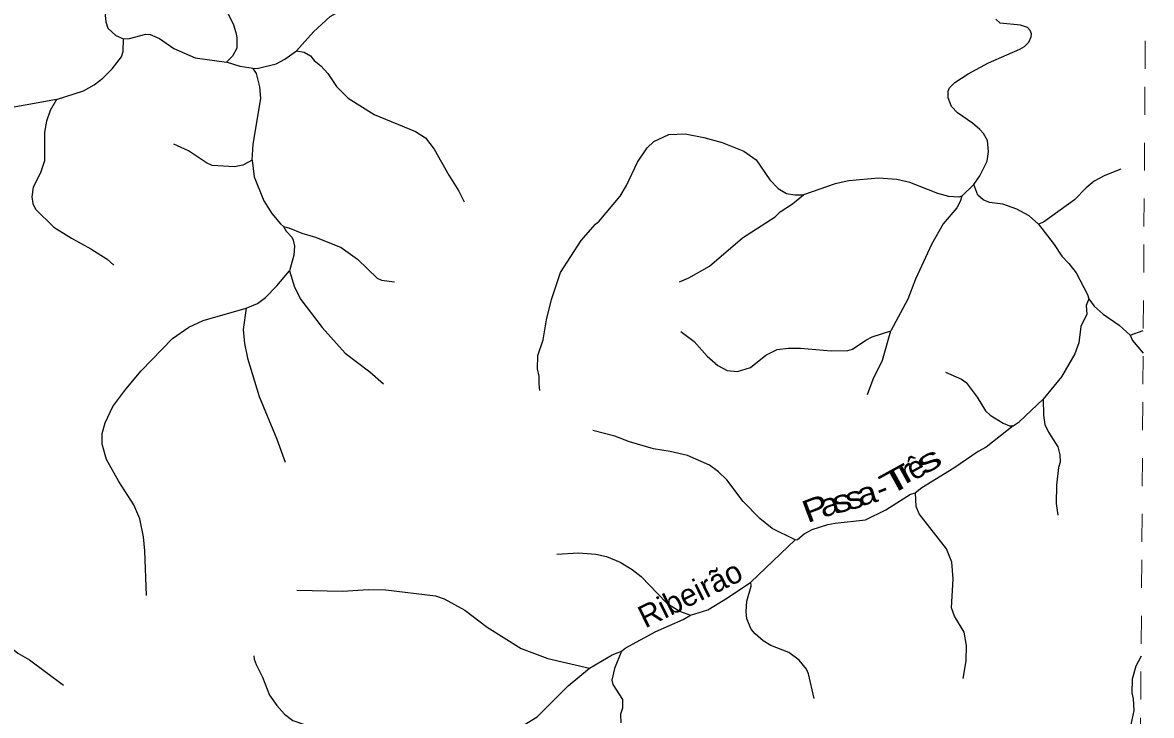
# Model space of a CAD drawing. Extents: x 577 to 602.9, y 7483.8 to 7511.6.
# Drawn here: x 598.702 to 602.746, y 7488.237 to 7490.719 of the extents above; entities that cross this region are included whole.
import ezdxf
from ezdxf.enums import TextEntityAlignment as Align

# ---------------------------------------------------------------- set-up
doc = ezdxf.new("R2010")
doc.units = 0
doc.header["$LTSCALE"] = 0.032
doc.linetypes.add('SHORT_DASHED', pattern=[2.7, 1.5, -1.2])
doc.layers.add('53', color=7, linetype='SHORT_DASHED', lineweight=13)
doc.layers.add('7', color=7, linetype='Continuous', lineweight=25)
doc.layers.add('61', color=7, linetype='Continuous')

msp = doc.modelspace()

# ---------------------------------------------------------------- linework, layer by layer
at = {"layer": '53'}
msp.add_lwpolyline([(602.6772, 7483.7754), (602.681, 7484.3402), (602.6848, 7484.9051), (602.6886, 7485.4699), (602.6924, 7486.0347), (602.6962, 7486.5996), (602.7, 7487.1644), (602.7038, 7487.7293), (602.7076, 7488.2941), (602.7115, 7488.859), (602.7153, 7489.4238), (602.7191, 7489.9887), (602.7229, 7490.5535), (602.7267, 7491.1183), (602.7305, 7491.6832), (602.7343, 7492.248), (602.7381, 7492.8129), (602.7419, 7493.3777), (602.7457, 7493.9426)], dxfattribs=at)
at = {"layer": '7'}
for p, q in [((598.8234, 7490.4436), (598.5928, 7490.4018)), ((602.6701, 7489.6), (602.7166, 7489.6157)), ((601.311, 7488.7142), (601.4702, 7488.866))]:
    msp.add_line(p, q, dxfattribs=at)
for points in [[(599.0212, 7491.3305), (599.0171, 7491.3174), (599.0196, 7491.091), (599.0131, 7491.0509), (599.0106, 7490.9929), (599.0155, 7490.9504), (599.0245, 7490.9169), (599.0294, 7490.8556), (599.0253, 7490.8302), (599.0032, 7490.7746), (598.9975, 7490.7444), (599, 7490.7215), (599.0081, 7490.6994), (599.0359, 7490.6733), (599.0637, 7490.661)], [(599.6833, 7490.6185), (599.7438, 7490.6856), (599.8035, 7490.7411), (599.8803, 7490.7828), (599.9375, 7490.8041), (599.9686, 7490.8196), (600.0152, 7490.849), (600.043, 7490.8719), (600.0822, 7490.9226), (600.0969, 7490.9488), (600.1231, 7491.0248), (600.1296, 7491.055), (600.1476, 7491.0951), (600.1582, 7491.1335), (600.1815, 7491.1819)], [(599.3357, 7490.9565), (599.3384, 7490.9349), (599.3547, 7490.8964), (599.4005, 7490.8065), (599.4397, 7490.7477), (599.4577, 7490.7109), (599.4659, 7490.6839), (599.47, 7490.6651), (599.47, 7490.6275), (599.4545, 7490.5989), (599.4321, 7490.577)], [(602.1094, 7490.1395), (602.1315, 7490.1698), (602.1568, 7490.2229), (602.1625, 7490.2572), (602.1584, 7490.2965), (602.1437, 7490.3218), (602.1306, 7490.3357), (602.1045, 7490.3586), (602.0514, 7490.3962), (602.0293, 7490.4191), (602.0178, 7490.4493), (602.0178, 7490.4738), (602.0219, 7490.4853), (602.0415, 7490.5041), (602.089, 7490.536), (602.1625, 7490.5752), (602.2745, 7490.6242), (602.2909, 7490.6332), (602.3064, 7490.6488), (602.3154, 7490.6684), (602.3162, 7490.679), (602.3113, 7490.6913), (602.3015, 7490.7019), (602.277, 7490.7093), (602.2042, 7490.7166), (602.1879, 7490.7313)], [(598.8234, 7490.4436), (598.9207, 7490.4747), (598.9583, 7490.4959), (598.9893, 7490.5196), (599.0229, 7490.5539), (599.0564, 7490.5965), (599.0629, 7490.6161), (599.0637, 7490.661)], [(599.0637, 7490.661), (599.085, 7490.662), (599.1438, 7490.6774), (599.1594, 7490.6766), (599.1929, 7490.6618), (599.2436, 7490.6267), (599.3204, 7490.5932), (599.4321, 7490.577)], [(599.528, 7490.5548), (599.5476, 7490.5556), (599.6106, 7490.5711), (599.6416, 7490.5883), (599.6833, 7490.6185)], [(599.6833, 7490.6185), (599.7103, 7490.6136), (599.7332, 7490.6005), (599.7471, 7490.5834), (599.7708, 7490.5646), (599.7953, 7490.5368), (599.8264, 7490.4902), (599.8689, 7490.4485), (599.9621, 7490.3896), (600.1092, 7490.3292), (600.1452, 7490.3063), (600.177, 7490.2654), (600.2285, 7490.1722), (600.2653, 7490.115), (600.2834, 7490.077)], [(599.528, 7490.5548), (599.4814, 7490.5621), (599.4321, 7490.577)], [(599.5247, 7490.2262), (599.5288, 7490.2842), (599.5558, 7490.4469), (599.5525, 7490.4886), (599.5403, 7490.537), (599.528, 7490.5548)], [(598.8234, 7490.4436), (598.8005, 7490.4044), (598.7874, 7490.3659), (598.7809, 7490.3267), (598.7809, 7490.2245), (598.7662, 7490.1812), (598.74, 7490.1297), (598.7351, 7490.0954), (598.7384, 7490.0709), (598.7482, 7490.0504), (598.8144, 7489.9859), (598.8774, 7489.9466), (598.9468, 7489.909), (599.0049, 7489.8714), (599.0288, 7489.8499)], [(600.5548, 7489.4014), (600.553, 7489.4235), (600.5522, 7489.4521), (600.5465, 7489.4791), (600.5481, 7489.5265), (600.5669, 7489.5829), (600.5792, 7489.6548), (600.5972, 7489.7275), (600.6291, 7489.824), (600.7034, 7489.9384), (600.7541, 7489.9973), (600.7672, 7490.0079), (600.8424, 7490.0978), (600.8653, 7490.1354), (600.9045, 7490.2188), (600.9389, 7490.2703), (600.9634, 7490.2932), (601.0173, 7490.3177), (601.0754, 7490.3202), (601.1424, 7490.3079), (601.2086, 7490.2899), (601.2863, 7490.258), (601.3296, 7490.227), (601.3794, 7490.1559), (601.4089, 7490.1248), (601.4383, 7490.1068), (601.4689, 7490.1019), (601.4992, 7490.102)], [(599.5247, 7490.2262), (599.4912, 7490.2082), (599.4618, 7490.2025), (599.3817, 7490.2074), (599.3605, 7490.2172), (599.2967, 7490.2597), (599.2436, 7490.2842)], [(599.5247, 7490.2262), (599.5313, 7490.1665), (599.5664, 7490.0807), (599.595, 7490.0357), (599.6261, 7489.9981), (599.6371, 7489.9883)], [(602.6367, 7490.1937), (602.5786, 7490.1714), (602.541, 7490.151), (602.5124, 7490.1273), (602.4699, 7490.0839), (602.3588, 7490.004), (602.3415, 7489.9973)], [(602.0662, 7490.0978), (602.0554, 7490.0937), (602.0195, 7490.0962), (601.9811, 7490.1068), (601.8805, 7490.1461), (601.8339, 7490.1567), (601.7685, 7490.1624), (601.6623, 7490.1526), (601.6132, 7490.142), (601.4992, 7490.102)], [(602.3415, 7489.9973), (602.3072, 7490.0267), (602.2639, 7490.0504), (602.2132, 7490.0692), (602.1658, 7490.0749), (602.1429, 7490.0848), (602.1241, 7490.1011), (602.1094, 7490.1395), (602.0662, 7490.0978)], [(601.0554, 7489.7903), (601.0893, 7489.8044), (601.1628, 7489.8469), (601.2814, 7489.9482), (601.3974, 7490.0235), (601.4162, 7490.0414), (601.4604, 7490.07), (601.4992, 7490.102)], [(602.0662, 7490.0978), (602.0603, 7490.0782), (602.0481, 7490.0561), (601.9999, 7489.9981), (601.9574, 7489.9237), (601.9001, 7489.8003), (601.8732, 7489.7284), (601.8119, 7489.6147)], [(599.6371, 7489.9883), (599.6564, 7489.9834), (599.7021, 7489.9646), (599.752, 7489.9499), (599.8435, 7489.9139), (599.9024, 7489.8714), (599.9727, 7489.8036), (599.9882, 7489.7962), (600.0344, 7489.7904)], [(599.6371, 7489.9883), (599.6465, 7489.972), (599.6662, 7489.9507), (599.6719, 7489.9393), (599.676, 7489.918), (599.6735, 7489.8861), (599.6581, 7489.8293)], [(602.3415, 7489.9973), (602.3979, 7489.9245), (602.4249, 7489.882), (602.4502, 7489.8567), (602.4756, 7489.8232), (602.5173, 7489.7455), (602.5211, 7489.73)], [(599.5035, 7489.6965), (599.5435, 7489.7128), (599.5722, 7489.7341), (599.613, 7489.7758), (599.6581, 7489.8293)], [(599.6581, 7489.8293), (599.6768, 7489.7717), (599.6989, 7489.7267), (599.7749, 7489.627), (599.8574, 7489.5346), (599.9465, 7489.4684), (599.9945, 7489.4248)], [(602.5211, 7489.73), (602.5116, 7489.7063), (602.514, 7489.6744), (602.4928, 7489.6303), (602.4854, 7489.5722), (602.4715, 7489.5322), (602.4241, 7489.4504), (602.3579, 7489.3703)], [(602.5211, 7489.73), (602.541, 7489.7038), (602.5729, 7489.6744), (602.6301, 7489.6352), (602.6701, 7489.6)], [(599.1458, 7488.667), (599.1406, 7488.8268), (599.1357, 7488.8766), (599.1226, 7488.9412), (599.1005, 7488.9911), (599.0474, 7489.0753), (599.0032, 7489.1545), (598.9869, 7489.2085), (598.9877, 7489.2477), (598.9983, 7489.2853), (599.0261, 7489.3434), (599.0719, 7489.4055), (599.1275, 7489.4717), (599.2395, 7489.587), (599.2983, 7489.6278), (599.349, 7489.6523), (599.5035, 7489.6965)], [(599.5035, 7489.6965), (599.4929, 7489.6197), (599.497, 7489.569), (599.5084, 7489.5167), (599.5493, 7489.3793), (599.613, 7489.2265), (599.6428, 7489.1448)], [(601.0603, 7489.6121), (601.1081, 7489.5763), (601.1547, 7489.524), (601.1923, 7489.4905), (601.2266, 7489.4725), (601.2634, 7489.4692), (601.3091, 7489.484), (601.3647, 7489.5273), (601.4056, 7489.5477), (601.4448, 7489.5526), (601.489, 7489.5526), (601.5985, 7489.5428), (601.6582, 7489.5445), (601.6745, 7489.5494), (601.7228, 7489.5821), (601.7456, 7489.5935), (601.8119, 7489.6147)], [(601.7293, 7489.3867), (601.7489, 7489.4415), (601.7824, 7489.5093), (601.8119, 7489.6147)], [(602.6701, 7489.6), (602.6783, 7489.5804), (602.7161, 7489.5353)], [(602.0077, 7489.4666), (602.0652, 7489.4423), (602.0816, 7489.43), (602.1217, 7489.3777), (602.1519, 7489.3287), (602.1682, 7489.3123), (602.2148, 7489.2837), (602.2377, 7489.2747), (602.2508, 7489.2747)], [(602.2508, 7489.2747), (602.2721, 7489.2886), (602.3579, 7489.3703)], [(602.3579, 7489.3703), (602.3587, 7489.3123), (602.3644, 7489.2796), (602.3767, 7489.2518), (602.411, 7489.1995), (602.4176, 7489.1709), (602.4184, 7489.1447), (602.4126, 7489.1251), (602.4053, 7489.0622), (602.4045, 7488.9968), (602.4106, 7488.9548)], [(601.4702, 7488.866), (601.3876, 7488.9069), (601.3427, 7488.9428), (601.283, 7489.0041), (601.225, 7489.0818), (601.1955, 7489.1104), (601.1628, 7489.1341), (601.0844, 7489.1684), (601.0214, 7489.1832), (600.9618, 7489.1921), (600.8767, 7489.2175), (600.8236, 7489.2379), (600.7454, 7489.2577)], [(602.2508, 7489.2747), (602.1543, 7489.1979), (602.1249, 7489.1832), (602.0383, 7489.1227), (601.9238, 7489.0524), (601.9006, 7489.0348)], [(601.4702, 7488.866), (601.4784, 7488.8676), (601.5021, 7488.8873), (601.5307, 7488.9036), (601.5862, 7488.9208), (601.6124, 7488.9265), (601.7219, 7488.9379), (601.7947, 7488.9739), (601.8822, 7489.0295), (601.9006, 7489.0348)], [(602.0709, 7488.3694), (602.0816, 7488.4328), (602.0832, 7488.4875), (602.0751, 7488.535), (602.0407, 7488.593), (602.0301, 7488.6224), (602.0358, 7488.727), (602.0309, 7488.7859), (602.0121, 7488.8341), (601.914, 7488.9592), (601.9034, 7488.9853), (601.9006, 7489.0348)], [(598.0403, 7488.8562), (598.0992, 7488.821), (598.1425, 7488.8039), (598.1801, 7488.7998), (598.297, 7488.8022), (598.346, 7488.799), (598.3861, 7488.79), (598.4221, 7488.7761), (598.4556, 7488.7499), (598.4768, 7488.7197), (598.5259, 7488.6044), (598.5373, 7488.584), (598.5569, 7488.5611), (598.6338, 7488.4965), (598.6591, 7488.4818), (598.6853, 7488.4598), (598.727, 7488.436), (598.8484, 7488.346)], [(600.6156, 7488.8155), (600.6936, 7488.8202), (600.7558, 7488.8153), (600.7942, 7488.8063), (600.8432, 7488.7867), (600.8857, 7488.7606), (600.9184, 7488.7352), (601.0083, 7488.6412), (601.0549, 7488.611), (601.095, 7488.5963)], [(601.095, 7488.5963), (601.1563, 7488.6159), (601.2274, 7488.6584), (601.311, 7488.7142)], [(601.538, 7488.2982), (601.5176, 7488.3862), (601.5102, 7488.4025), (601.4841, 7488.4352), (601.4473, 7488.4622), (601.3827, 7488.4884), (601.3549, 7488.5047), (601.3263, 7488.5292), (601.3124, 7488.5464), (601.2969, 7488.5832), (601.2944, 7488.6102), (601.2969, 7488.6469), (601.3116, 7488.7001), (601.311, 7488.7142)], [(599.6841, 7488.6857), (599.8476, 7488.6821), (599.9416, 7488.6886), (600.0029, 7488.6878), (600.1811, 7488.6657), (600.2122, 7488.6551), (600.2858, 7488.6142), (600.3659, 7488.5538), (600.4885, 7488.4769), (600.5841, 7488.441), (600.7329, 7488.4066)], [(600.8473, 7488.4671), (600.8612, 7488.4777), (600.9707, 7488.5374), (601.0688, 7488.5815), (601.095, 7488.5963)], [(599.5304, 7488.4512), (599.5313, 7488.4385), (599.5386, 7488.4197), (599.5615, 7488.3739), (599.5869, 7488.3102), (599.613, 7488.2726), (599.64, 7488.2415), (599.6702, 7488.2194), (599.7152, 7488.2031), (599.792, 7488.1965), (599.8163, 7488.1926)], [(600.7329, 7488.4066), (600.8138, 7488.454), (600.8351, 7488.4622), (600.8473, 7488.4671)], [(600.8473, 7488.4671), (600.822, 7488.405), (600.813, 7488.3641), (600.8163, 7488.3478), (600.8506, 7488.2946), (600.8506, 7488.2628), (600.844, 7488.2415), (600.8457, 7488.2113)], [(602.7087, 7488.4494), (602.6897, 7488.4132), (602.6767, 7488.3674), (602.675, 7488.3183), (602.6799, 7488.2971), (602.6824, 7488.2546), (602.6652, 7488.172), (602.6652, 7488.145), (602.6701, 7488.1173), (602.7004, 7488.0445), (602.7058, 7488.0245)], [(600.4623, 7488.1925), (600.4926, 7488.2006), (600.5449, 7488.2325), (600.6569, 7488.3429), (600.7329, 7488.4066)]]:
    msp.add_lwpolyline(points, dxfattribs=at)

# ---------------------------------------------------------------- texts
at = {"layer": '61'}
for s, rotation, p in [('ê', 28.782, (601.9202, 7489.0911)), ('Ribeirão', 26.406, (601.1111, 7488.637))]:
    msp.add_text(s, height=0.08, rotation=rotation, dxfattribs=at).set_placement(p, align=Align.CENTER)
for s, rotation, width, p in [('s', 28.782, 1.6, (601.9664, 7489.1174)), ('T', 28.782, 1.75, (601.8502, 7489.0464)), ('r', 28.782, 1.55, (601.8861, 7489.0768)), ('s', 15.437, 1.2, (601.6913, 7488.9794)), ('a', 15.813, 1.2, (601.7364, 7488.995)), ('-', 21.637, 1.1, (601.7934, 7489.0149)), ('P', 20.683, 1.3, (601.5565, 7488.9414)), ('a', 16.966, 1.2, (601.6025, 7488.9554)), ('s', 16.966, 1.25, (601.6476, 7488.9677))]:
    msp.add_text(s, height=0.08, rotation=rotation, dxfattribs=dict(at, width=width)).set_placement(p, align=Align.CENTER)

doc.saveas('drawing.dxf')
